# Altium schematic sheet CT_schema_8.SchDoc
size 274 x 160 mm
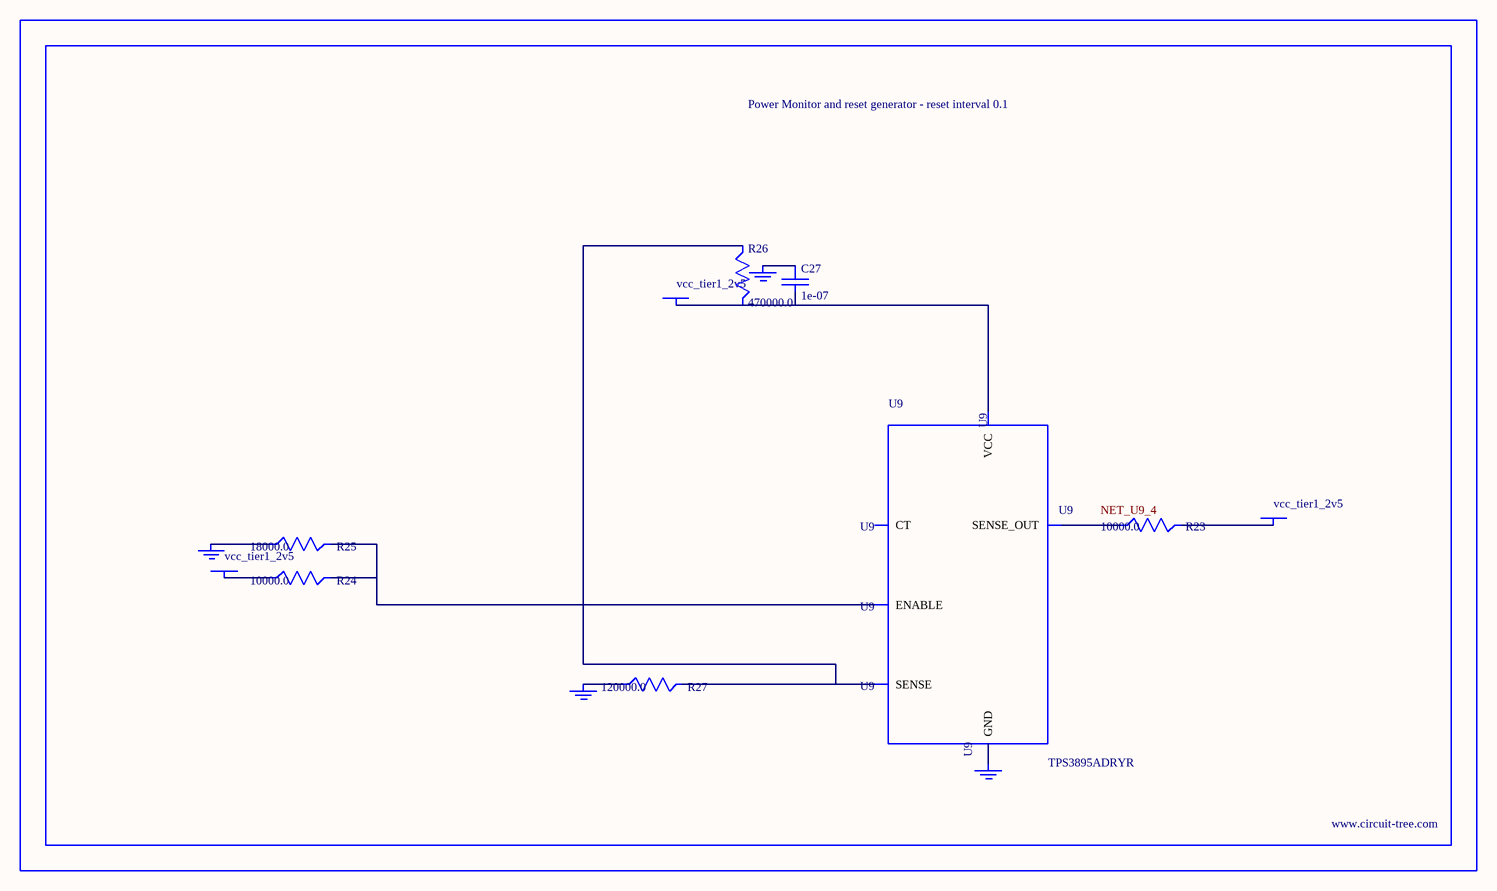
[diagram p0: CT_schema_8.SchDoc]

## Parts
BORDER7  (no value)
C27  1e-07  [C0402]
GND_INSTANCE_7_0  (no value)
GND_INSTANCE_7_1  (no value)
GND_INSTANCE_7_2  (no value)
GND_INSTANCE_7_3  (no value)
POWER_INSTANCE_7_0  vcc_tier1_2v5
POWER_INSTANCE_7_1  vcc_tier1_2v5
POWER_INSTANCE_7_2  vcc_tier1_2v5
R23  10000.0  [R0603]
R24  10000.0  [R0603]
R25  18000.0  [R0603]
R26  470000.0  [R0603]
R27  120000.0  [R0603]
U9  TPS3895ADRYR  [SON-6]

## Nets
NetC27_1: C27.1 GND_INSTANCE_7_2.0(GND)
NetC27_2: C27.2 POWER_INSTANCE_7_2.0(PWR) R26.2 U9.6(VCC)
NetGND_INSTANCE_7_0_0: GND_INSTANCE_7_0.0(GND) R25.1
NetGND_INSTANCE_7_1_0: GND_INSTANCE_7_1.0(GND) R27.1
NetGND_INSTANCE_7_3_0: GND_INSTANCE_7_3.0(GND) U9.2(GND)
NetPOWER_INSTANCE_7_0_0: POWER_INSTANCE_7_0.0(PWR) R24.1
NetPOWER_INSTANCE_7_1_0: POWER_INSTANCE_7_1.0(PWR) R23.2
NetR23_1: R23.1 U9.4(SENSE_OUT)
NetR24_2: R24.2 R25.2 U9.1(ENABLE)
NetR26_1: R26.1 R27.2 U9.3(SENSE)

Not connected (* = marked no-connect by the designer): U9 5(CT)

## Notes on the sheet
- Labels drawn without touching a wire or pin: NET_U9_4

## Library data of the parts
BORDER7 = BORDER_PAGE7
C27 = C0402C104K3RACTU
GND_INSTANCE_7_0-GND_INSTANCE_7_3 = GND
POWER_INSTANCE_7_0-POWER_INSTANCE_7_2 = PWR
R23 R24 = RC0603JR-0710KL
R25 = RC0603JR-0718KL
R26 = RC0603JR-07470KL
R27 = RC0603JR-07120KL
